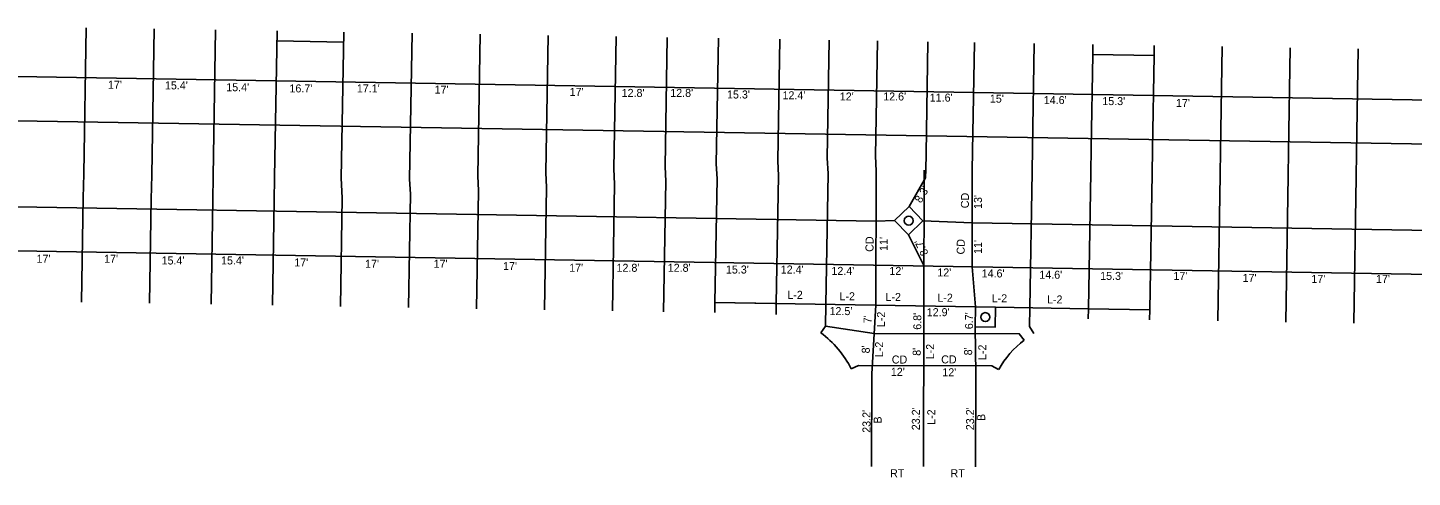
# Model space of a CAD drawing. Extents: x 4995357 to 4999033, y 3881202 to 3881750.
# Drawn here: x 4997128.9 to 4997475, y 3881587.8 to 3881700.1 of the extents above; entities that cross this region are included whole.
import ezdxf

# ---------------------------------------------------------------- set-up
doc = ezdxf.new("R2010")
doc.units = 0
for name, color, linetype in [('dsn3DCenterLine', 7, 'Continuous'), ('dsn3DCurbFormgrade', 7, 'Continuous'), ('dsn3DCurbTop', 7, 'Continuous'), ('dsn3DDitchFront', 7, 'Continuous'), ('dsn3DDNC', 7, 'Continuous'), ('dsn3DExistingPvmtBtm', 7, 'Continuous'), ('dsn3DGroundLineIntercept', 7, 'Continuous'), ('dsn3DIntakeWell', 7, 'Continuous')]:
    doc.layers.add(name, color=color, linetype=linetype)

msp = doc.modelspace()

# ---------------------------------------------------------------- linework, layer by layer
at = {"layer": 'dsn3DCurbFormgrade'}
for p, q in [((4997143.53, 3881700.06), (4997142.93, 3881663.57)), ((4997160.53, 3881699.78), (4997159.93, 3881663.29)), ((4997175.89, 3881699.53), (4997175.29, 3881663.03)), ((4997190.65, 3881662.78), (4997191.25, 3881699.27)), ((4997207.32, 3881662.5), (4997207.93, 3881698.99)), ((4997225, 3881698.71), (4997224.39, 3881662.25)), ((4997242, 3881698.43), (4997241.41, 3881663.1)), ((4997258.99, 3881698.15), (4997258.43, 3881663.96)), ((4997275.99, 3881697.86), (4997275.44, 3881664.81)), ((4997288.78, 3881697.65), (4997288.24, 3881665.45)), ((4997301.57, 3881697.44), (4997301.05, 3881666.09)), ((4997316.9, 3881697.18), (4997316.39, 3881666.85)), ((4997329.27, 3881696.98), (4997328.78, 3881667.47)), ((4997341.31, 3881696.78), (4997340.83, 3881668.08)), ((4997365.55, 3881696.38), (4997365.1, 3881669.29)), ((4997380.53, 3881696.13), (4997380.1, 3881670.04)), ((4997427.06, 3881669.35), (4997427.5, 3881695.35)), ((4997394.74, 3881669.89), (4997395.13, 3881693.38)), ((4997410.07, 3881669.63), (4997410.46, 3881693.13)), ((4997444.49, 3881695.06), (4997444.06, 3881669.07)), ((4997461.49, 3881694.78), (4997461.06, 3881668.79)), ((4997341.02, 3881664.3), (4997340.94, 3881630.78)), ((4997353.02, 3881664.54), (4997352.94, 3881630.58)), ((4997365.02, 3881664.38), (4997364.96, 3881640.38)), ((4997275.11, 3881629.37), (4997275.63, 3881661.03)), ((4997288.43, 3881661.67), (4997287.89, 3881629.16)), ((4997301.23, 3881662.31), (4997300.72, 3881631.44)), ((4997316.58, 3881663.08), (4997316.05, 3881631.19)), ((4997328.97, 3881663.7), (4997328.43, 3881630.98)), ((4997349.21, 3881655.44), (4997353.36, 3881662.57)), ((4997380, 3881664.13), (4997379.43, 3881630.14)), ((4997394.64, 3881663.89), (4997394.07, 3881629.89)), ((4997409.97, 3881663.63), (4997409.4, 3881629.64)), ((4997426.96, 3881663.35), (4997426.36, 3881626.86)), ((4997443.96, 3881663.07), (4997443.36, 3881626.57)), ((4997460.96, 3881662.79), (4997460.35, 3881626.29)), ((4997142.83, 3881657.57), (4997142.4, 3881631.57)), ((4997159.83, 3881657.29), (4997159.39, 3881631.29)), ((4997207.11, 3881630.5), (4997207.57, 3881657.63)), ((4997224.11, 3881630.22), (4997224.58, 3881658.48)), ((4997241.11, 3881629.93), (4997241.6, 3881659.33)), ((4997258.11, 3881629.65), (4997258.61, 3881660.18)), ((4997175.19, 3881657.03), (4997174.76, 3881631.04)), ((4997190.12, 3881630.78), (4997190.55, 3881656.78)), ((4997352.97, 3881640.58), (4997349.09, 3881648.37)), ((4997364.96, 3881640.38), (4997365.82, 3881630.36)), ((4997378, 3881622.11), (4997376.77, 3881623.69)), ((4997334.76, 3881614.89), (4997336.55, 3881615.78)), ((4997336.55, 3881615.78), (4997369.88, 3881615.7)), ((4997371.62, 3881614.72), (4997369.88, 3881615.7))]:
    msp.add_line(p, q, dxfattribs=at)
at = {"layer": 'dsn3DCurbTop'}
for p, q in [((4997340.83, 3881668.08), (4997341.02, 3881664.3)), ((4997353.46, 3881668.69), (4997353.39, 3881664.57)), ((4997365.02, 3881664.38), (4997365.1, 3881669.29)), ((4997380, 3881664.13), (4997380.1, 3881670.04)), ((4997394.64, 3881663.89), (4997394.74, 3881669.89)), ((4997409.97, 3881663.63), (4997410.07, 3881669.63)), ((4997426.96, 3881663.35), (4997427.06, 3881669.35)), ((4997443.96, 3881663.07), (4997444.06, 3881669.07)), ((4997461.06, 3881668.79), (4997460.96, 3881662.79)), ((4997275.44, 3881664.81), (4997275.63, 3881661.03)), ((4997288.24, 3881665.45), (4997288.43, 3881661.67)), ((4997301.05, 3881666.09), (4997301.23, 3881662.31)), ((4997316.39, 3881666.85), (4997316.58, 3881663.08)), ((4997328.78, 3881667.47), (4997328.97, 3881663.7)), ((4997353.39, 3881664.57), (4997353.36, 3881662.57)), ((4997142.83, 3881657.57), (4997142.93, 3881663.57)), ((4997159.83, 3881657.29), (4997159.93, 3881663.29)), ((4997175.19, 3881657.03), (4997175.29, 3881663.03)), ((4997190.65, 3881662.78), (4997190.55, 3881656.78)), ((4997207.57, 3881657.63), (4997207.32, 3881662.5)), ((4997224.39, 3881662.25), (4997224.58, 3881658.48)), ((4997241.41, 3881663.1), (4997241.6, 3881659.33)), ((4997258.43, 3881663.96), (4997258.61, 3881660.18)), ((4997328.43, 3881630.98), (4997328.34, 3881625.53)), ((4997327.15, 3881623.91), (4997328.34, 3881625.53)), ((4997380.4, 3881623.77), (4997379.36, 3881625.47))]:
    msp.add_line(p, q, dxfattribs=at)
msp.add_arc((4997458.39, 3880682.19), 989, 78.42004, 89.04825, dxfattribs=at)
at = {"layer": 'dsn3DDitchFront'}
msp.add_line((4997353.92, 3881696.57), (4997353.46, 3881668.71), dxfattribs=at)
at = {"layer": 'dsn3DDNC'}
for p, q in [((4996800.58, 3881693.26), (4997475, 3881682.06)), ((4996800.62, 3881682.26), (4997474.82, 3881671.06)), ((4996408.52, 3881656.27), (4997479.7, 3881638.47)), ((4997027.54, 3881656.98), (4997340.99, 3881651.78)), ((4997340.99, 3881651.78), (4997345.61, 3881651.96)), ((4997352.68, 3881651.84), (4997364.99, 3881651.38)), ((4997364.99, 3881651.38), (4997479.89, 3881649.47)), ((4997300.72, 3881631.44), (4997365.82, 3881630.36)), ((4997340.94, 3881630.78), (4997339.9, 3881613.71)), ((4997352.94, 3881630.58), (4997352.85, 3881590.52)), ((4997370.82, 3881630.28), (4997394.07, 3881629.89)), ((4997379.43, 3881630.14), (4997379.36, 3881625.47)), ((4997365.74, 3881625.36), (4997365.9, 3881613.65)), ((4997365.9, 3881613.65), (4997365.85, 3881590.49))]:
    msp.add_line(p, q, dxfattribs=at)
msp.add_lwpolyline([(4997395.17, 3881695.88), (4997395.13, 3881693.38), (4997410.46, 3881693.13), (4997410.51, 3881695.63)], dxfattribs=at)
msp.add_arc((4997458.39, 3880682.19), 1000, 78.42004, 89.04825, dxfattribs=at)
at = {"layer": 'dsn3DExistingPvmtBtm'}
for p, q in [((4997191.21, 3881696.77), (4997207.89, 3881696.49)), ((4997339.85, 3881590.55), (4997339.9, 3881613.71))]:
    msp.add_line(p, q, dxfattribs=at)
for points in [[(4997349.21, 3881655.44), (4997352.68, 3881651.84), (4997349.09, 3881648.37), (4997345.61, 3881651.96)], [(4997365.82, 3881630.36), (4997370.82, 3881630.28), (4997370.74, 3881625.28), (4997365.74, 3881625.36)]]:
    msp.add_lwpolyline(points, close=True, dxfattribs=at)
for points in [[(4997300.68, 3881628.94), (4997300.72, 3881631.44), (4997316.05, 3881631.19), (4997316.01, 3881628.48)], [(4997394.03, 3881627.39), (4997394.07, 3881629.89), (4997409.4, 3881629.64), (4997409.36, 3881627.14)]]:
    msp.add_lwpolyline(points, dxfattribs=at)
for centre in [(4997349.15, 3881651.9), (4997368.28, 3881627.82)]:
    msp.add_circle(centre, 1.12, dxfattribs=at)
at = {"layer": 'dsn3DGroundLineIntercept'}
for p, q in [((4997328.34, 3881625.53), (4997340.51, 3881623.77)), ((4997340.51, 3881623.77), (4997376.77, 3881623.69))]:
    msp.add_line(p, q, dxfattribs=at)
at = {"layer": 'dsn3DIntakeWell'}
for points in [[(4997327.15, 3881623.91), (4997328.34, 3881625.53), (4997340.51, 3881623.77), (4997376.77, 3881623.69), (4997378, 3881622.11)], [(4997371.62, 3881614.72), (4997369.88, 3881615.7), (4997336.55, 3881615.78), (4997334.76, 3881614.89)]]:
    msp.add_lwpolyline(points, dxfattribs=at)
for centre, start, end in [((4997312.38, 3881603.75), 26.4634, 53.7789), ((4997393.38, 3881602.4), 127.9645, 150.484)]:
    msp.add_arc(centre, 25, start, end, dxfattribs=at)

# ---------------------------------------------------------------- texts
at = {"layer": 'dsn3DCenterLine'}
for s, p in [("17'", (4997149.01, 3881684.83)), ("15.4'", (4997163.24, 3881684.67)), ("15.4'", (4997178.57, 3881684.22)), ("16.7'", (4997194.36, 3881683.92)), ("17.1'", (4997211.21, 3881683.92)), ("17'", (4997230.65, 3881683.61)), ("17'", (4997264.4, 3881683.05)), ("12.8'", (4997277.39, 3881682.79)), ("12.8'", (4997289.54, 3881682.79)), ("15.3'", (4997303.73, 3881682.4)), ("12.4'", (4997317.6, 3881682.2)), ("12'", (4997331.91, 3881681.9)), ("12.6'", (4997342.77, 3881681.9)), ("11.6'", (4997354.39, 3881681.62)), ("15'", (4997369.42, 3881681.36)), ("14.6'", (4997382.89, 3881681.01)), ("15.3'", (4997397.52, 3881680.75)), ("17'", (4997415.94, 3881680.28)), ("17'", (4997131.14, 3881641.4)), ("17'", (4997148.04, 3881641.4)), ("15.4'", (4997162.4, 3881640.97)), ("15.4'", (4997177.27, 3881640.97)), ("17'", (4997195.56, 3881640.47)), ("17'", (4997213.26, 3881640.13)), ("17'", (4997230.4, 3881640.13)), ("17'", (4997247.75, 3881639.58)), ("17'", (4997264.27, 3881639.14)), ("12.8'", (4997276.11, 3881639.14)), ("12.8'", (4997288.91, 3881639.14)), ("15.3'", (4997303.45, 3881638.71)), ("12.4'", (4997317.15, 3881638.71)), ("12.4'", (4997329.82, 3881638.36)), ("12'", (4997344.31, 3881638.36)), ("12'", (4997356.29, 3881637.98)), ("14.6'", (4997367.37, 3881637.73)), ("14.6'", (4997381.78, 3881637.41)), ("15.3'", (4997396.99, 3881637.11)), ("17'", (4997415.3, 3881637.11)), ("17'", (4997432.59, 3881636.61)), ("17'", (4997449.78, 3881636.36)), ("17'", (4997465.93, 3881636.36)), ('L-2', (4997318.8, 3881632.39)), ('L-2', (4997331.83, 3881632.04)), ('L-2', (4997343.33, 3881631.86)), ('L-2', (4997356.3, 3881631.67)), ('L-2', (4997369.88, 3881631.52)), ('L-2', (4997383.7, 3881631.24)), ("12.5'", (4997329.35, 3881628.33)), ("12.9'", (4997353.64, 3881628.06)), ('CD', (4997344.91, 3881616.24)), ('CD', (4997357.25, 3881616.27)), ("12'", (4997344.67, 3881613.17)), ("12'", (4997357.54, 3881613.06)), ('RT', (4997344.48, 3881587.85)), ('RT', (4997359.59, 3881587.85))]:
    msp.add_text(s, height=2, dxfattribs=at).set_placement(p)
for s, rotation, p in [("8.3'", 59.7104, (4997352.22, 3881656.14)), ('CD', 89.6064, (4997364.18, 3881654.99)), ("13'", 90, (4997367.44, 3881654.82)), ('CD', 89.6064, (4997340.33, 3881644.11)), ("11'", 90, (4997343.88, 3881644.36)), ('CD', 89.6064, (4997363.12, 3881643.46)), ("11'", 90, (4997367.44, 3881643.6)), ("8.7'", 116.46, (4997354.14, 3881643.74)), ("7'", 90, (4997339.87, 3881626.28)), ('L-2', 90, (4997343.22, 3881625.33)), ("6.8'", 90, (4997352.29, 3881624.67)), ("6.7'", 90, (4997365.21, 3881624.81)), ("8'", 90, (4997339.41, 3881618.77)), ('L-2', 90, (4997342.75, 3881617.83)), ("8'", 90, (4997352.14, 3881618.17)), ('L-2', 90, (4997355.49, 3881617.29)), ("8'", 90, (4997364.99, 3881618.28)), ('L-2', 90, (4997368.54, 3881617.11)), ("23.2'", 90, (4997339.58, 3881598.95)), ('B', 90, (4997342.37, 3881601.25)), ("23.2'", 90, (4997351.92, 3881599.59)), ('L-2', 90, (4997355.77, 3881600.93)), ("23.2'", 90, (4997365.47, 3881599.6)), ('B', 90, (4997368.26, 3881601.89))]:
    msp.add_text(s, height=2, rotation=rotation, dxfattribs=at).set_placement(p)

doc.saveas('drawing.dxf')
